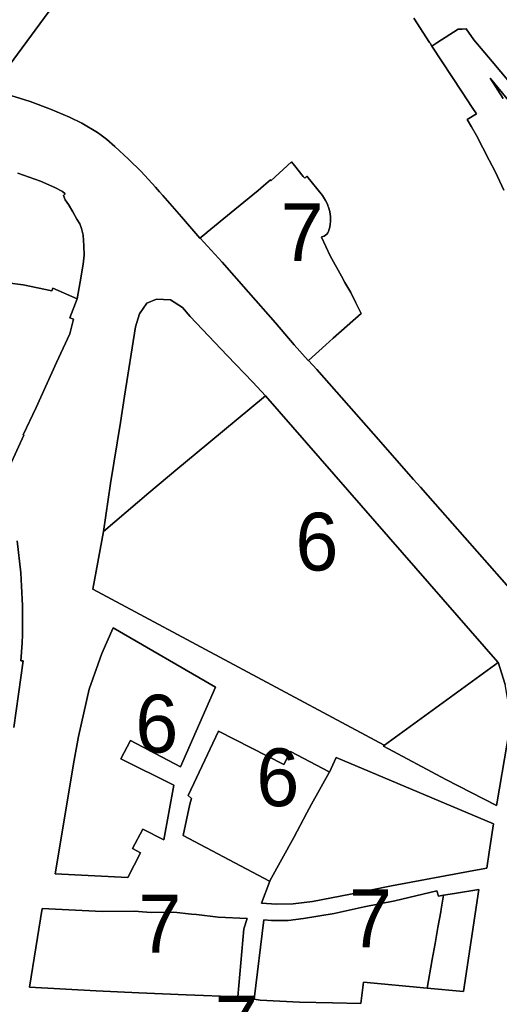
# Model space of a CAD drawing. Extents: x 598968 to 613553, y 4409678 to 4430833.
# Drawn here: x 607378.5 to 607478.1, y 4416577.8 to 4416782.2 of the extents above; entities that cross this region are included whole.
import ezdxf

# ---------------------------------------------------------------- set-up
doc = ezdxf.new("R2010")
doc.units = 0
for name, color, linetype in [('1', 7, 'Continuous'), ('ZONA 2. CARRERS DE CASES. Cases de trast', 7, 'Continuous'), ('ZONA 6. EDIFICIS DE PISOS_ AÏLLATS I EN PARCEL.LES', 7, 'Continuous'), ('ZONA 7. CONJUNTS AMB ORDENACIONS ESPECÍFIQUES', 7, 'Continuous')]:
    doc.layers.add(name, color=color, linetype=linetype)

msp = doc.modelspace()

# ---------------------------------------------------------------- linework, layer by layer
at = {"layer": '1'}
for points in [[(607386.3243, 4416786.4145), (607372.5667, 4416767.6727), (607380.6335, 4416765.184), (607384.899, 4416763.6217), (607388.8289, 4416761.9318), (607391.3789, 4416760.6968), (607394.6589, 4416758.7519), (607395.4182, 4416758.1945), (607396.5093, 4416757.3936), (607398.2639, 4416755.862), (607401.1232, 4416753.2226), (607403.6938, 4416750.6721), (607406.7038, 4416747.4072), (607407.5059, 4416746.4781), (607408.2188, 4416745.6523), (607412.0788, 4416741.2424), (607415.9387, 4416736.8325), (607416.8851, 4416737.6114), (607417.4087, 4416738.0525), (607422.4268, 4416742.1721), (607425.0586, 4416744.3326), (607428.0586, 4416746.7226), (607429.1484, 4416747.704), (607430.6111, 4416748.9097), (607430.6985, 4416748.7604), (607434.9485, 4416752.7027), (607435.5801, 4416751.9204), (607437.4068, 4416749.6585), (607437.7184, 4416749.2727), (607437.944, 4416749.5035), (607438.1484, 4416749.7127), (607441.4284, 4416745.7128), (607442.0615, 4416744.6782), (607442.2899, 4416744.144), (607442.5094, 4416743.6507), (607442.5292, 4416743.5844), (607442.5384, 4416743.5629), (607442.6357, 4416743.2431), (607442.913, 4416742.332), (607442.9859, 4416741.7542), (607443.0509, 4416741.3987), (607443.0558, 4416741.1996), (607443.074, 4416741.0555), (607443.0646, 4416740.8449), (607443.0795, 4416740.246), (607443.0168, 4416739.7702), (607443.016, 4416739.7653), (607442.9284, 4416739.103), (607442.7434, 4416738.513), (607442.6391, 4416738.2084), (607442.4863, 4416737.9251), (607442.2891, 4416737.6706), (607442.053, 4416737.4518), (607441.7842, 4416737.2746), (607441.4901, 4416737.1434), (607441.2801, 4416737.0892), (607441.1784, 4416737.0629), (607442.0734, 4416735.103), (607442.9684, 4416733.143), (607445.3421, 4416728.9189), (607446.0534, 4416727.6531), (607447.2584, 4416725.5632), (607448.3584, 4416723.3782), (607449.3103, 4416721.4874), (607449.4584, 4416721.1933), (607446.5484, 4416718.6383), (607443.5885, 4416716.0332), (607442.1085, 4416714.7132), (607438.4787, 4416711.4215), (607440.2385, 4416709.5332), (607451.9935, 4416696.2036), (607460.3291, 4416686.7515), (607461.737, 4416685.155), (607465.8801, 4416680.4569), (607481.2278, 4416663.0529)], [(607372.5667, 4416767.6727), (607386.3243, 4416786.4145)], [(607460.3682, 4416782.4727), (607463.6508, 4416777.477), (607463.7616, 4416777.3084), (607464.1451, 4416776.7248), (607465.1361, 4416777.3659), (607469.5681, 4416780.233), (607470.4381, 4416780.253), (607471.228, 4416780.283), (607472.858, 4416777.973), (607476.6384, 4416773.4786), (607488.1231, 4416759.8249)], [(607479.0966, 4416746.7706), (607477.3231, 4416750.5584), (607476.0581, 4416753.0034), (607474.7181, 4416755.5633), (607473.3781, 4416758.1233), (607472.3422, 4416759.9156), (607471.4381, 4416761.4832), (607473.3881, 4416762.6532), (607472.5181, 4416763.9732), (607470.4281, 4416767.1631), (607464.1451, 4416776.7248), (607463.7616, 4416777.3084), (607463.6508, 4416777.477), (607460.3682, 4416782.4727)], [(607488.1231, 4416759.8249), (607476.6384, 4416773.4786), (607472.858, 4416777.973), (607471.228, 4416780.283), (607470.4381, 4416780.253), (607469.5681, 4416780.233), (607465.1361, 4416777.3659), (607464.1451, 4416776.7248), (607470.4281, 4416767.1631), (607472.5181, 4416763.9732), (607473.3881, 4416762.6532), (607471.4381, 4416761.4832), (607472.3422, 4416759.9156), (607473.3781, 4416758.1233), (607474.7181, 4416755.5633), (607476.0581, 4416753.0034), (607477.3231, 4416750.5584), (607479.0966, 4416746.7706)], [(607478.9204, 4416765.8107), (607476.2357, 4416770.0207), (607480.3837, 4416764.9799)], [(607480.3837, 4416764.9799), (607476.2357, 4416770.0207), (607478.9204, 4416765.8107)], [(607481.2278, 4416663.0529), (607465.8801, 4416680.4569), (607461.737, 4416685.155), (607460.3291, 4416686.7515), (607451.9935, 4416696.2036), (607440.2385, 4416709.5332), (607438.4787, 4416711.4215), (607438.4586, 4416711.4032), (607435.5186, 4416714.6931), (607431.6186, 4416719.213), (607426.0286, 4416725.6228), (607420.5887, 4416731.8127), (607415.9607, 4416736.8325), (607415.9387, 4416736.8325), (607412.0788, 4416741.2424), (607408.2188, 4416745.6523), (607407.5059, 4416746.4781), (607406.7038, 4416747.4072), (607403.6938, 4416750.6721), (607401.1232, 4416753.2226), (607398.2639, 4416755.862), (607396.5093, 4416757.3936), (607395.4182, 4416758.1945), (607394.6589, 4416758.7519), (607391.3789, 4416760.6968), (607388.8289, 4416761.9318), (607384.899, 4416763.6217), (607380.6335, 4416765.184), (607372.5667, 4416767.6727)], [(607375.9492, 4416727.5319), (607379.1992, 4416727.122), (607385.1291, 4416725.8721), (607385.3691, 4416726.4321), (607390.4491, 4416724.2122), (607391.049, 4416727.7322), (607391.669, 4416731.4322), (607391.879, 4416733.2821), (607391.789, 4416735.2221), (607391.699, 4416737.4321), (607391.339, 4416738.8321), (607390.969, 4416739.782), (607390.329, 4416740.772), (607389.549, 4416742.262), (607388.629, 4416743.842), (607387.919, 4416744.7819), (607387.579, 4416745.6519), (607387.8994, 4416746.0624), (607387.349, 4416746.4919), (607385.809, 4416747.3719), (607382.8291, 4416748.6718), (607378.1191, 4416750.2917)], [(607378.1191, 4416750.2917), (607382.8291, 4416748.6718), (607385.809, 4416747.3719), (607387.349, 4416746.4919), (607387.8994, 4416746.0624), (607387.579, 4416745.6519), (607387.919, 4416744.7819), (607388.629, 4416743.842), (607389.549, 4416742.262), (607390.329, 4416740.772), (607390.969, 4416739.782), (607391.339, 4416738.8321), (607391.699, 4416737.4321), (607391.789, 4416735.2221), (607391.879, 4416733.2821), (607391.669, 4416731.4322), (607391.049, 4416727.7322), (607390.4491, 4416724.2122), (607388.8791, 4416720.2722), (607389.6691, 4416719.9923), (607388.8791, 4416716.9523), (607386.1492, 4416711.0223), (607381.8792, 4416701.6823), (607379.1993, 4416695.9624), (607379.3593, 4416695.8924), (607376.4393, 4416689.5524)], [(607479.6885, 4416631.5449), (607477.7042, 4416619.78), (607477.5785, 4416619.035), (607467.0586, 4416624.4047), (607454.0687, 4416631.3444), (607454.2157, 4416631.5745), (607393.6692, 4416663.953), (607395.9292, 4416675.9129), (607397.3552, 4416685.8582), (607399.4308, 4416698.5534), (607400.2864, 4416704.0086), (607402.5439, 4416718.4025), (607403.3889, 4416721.0975), (607404.8689, 4416723.3525), (607406.8889, 4416724.1925), (607409.8088, 4416723.9926), (607412.3288, 4416722.4226), (607413.8888, 4416720.5527), (607421.6006, 4416712.4978), (607426.9452, 4416706.9156), (607429.5508, 4416704.0995), (607477.844, 4416648.7799), (607477.8784, 4416648.8046), (607479.3796, 4416644.1495)], [(607377.9694, 4416673.9526), (607378.7194, 4416667.3727), (607378.8894, 4416664.5627), (607379.0494, 4416660.5728), (607379.0694, 4416654.5328), (607378.9794, 4416652.7128), (607378.7095, 4416649.1029), (607379.2295, 4416649.0829), (607377.2595, 4416635.2131)]]:
    msp.add_lwpolyline(points, dxfattribs=at)
for points in [[(607429.5508, 4416704.0995), (607426.9452, 4416706.9156), (607421.6006, 4416712.4978), (607413.8888, 4416720.5527), (607412.3288, 4416722.4226), (607409.8088, 4416723.9926), (607406.8889, 4416724.1925), (607404.8689, 4416723.3525), (607403.3889, 4416721.0975), (607402.5439, 4416718.4025), (607400.2864, 4416704.0086), (607399.4308, 4416698.5534), (607397.3552, 4416685.8582), (607395.9292, 4416675.9129), (607405.2975, 4416683.9329), (607411.3642, 4416688.9774), (607414.9525, 4416691.961)], [(607389.7794, 4416628.4334), (607390.6994, 4416633.3733), (607392.9093, 4416643.1632), (607395.5593, 4416650.6132), (607397.9292, 4416655.9231), (607419.159, 4416643.6037), (607411.9192, 4416627.0538), (607401.4993, 4416632.5135), (607399.4693, 4416628.7435), (607410.5292, 4416623.2638), (607408.4293, 4416611.8939), (607404.0593, 4416614.1038), (607401.8898, 4416610.1073), (607403.6203, 4416609.1946), (607400.9294, 4416604.1138), (607385.8695, 4416604.8636)], [(607454.2157, 4416631.5745), (607454.0687, 4416631.3444), (607467.0586, 4416624.4047), (607477.5785, 4416619.035), (607477.7042, 4416619.78), (607479.6885, 4416631.5449), (607480.1985, 4416634.4299), (607480.1683, 4416638.1557), (607480.1589, 4416639.3209), (607479.3796, 4416644.1495), (607477.8784, 4416648.8046), (607477.844, 4416648.7799), (607477.8941, 4416648.7225), (607454.2707, 4416631.5451)], [(607419.789, 4416634.4738), (607433.3389, 4416627.5141), (607434.7889, 4416630.2541), (607442.7547, 4416626.0153), (607442.8405, 4416625.9719), (607444.2588, 4416628.9943), (607476.9429, 4416615.2265), (607476.0333, 4416609.3501), (607475.5186, 4416606.0251), (607472.817, 4416605.5206), (607455.7587, 4416602.3348), (607447.1988, 4416600.6347), (607439.2952, 4416599.1174), (607435.3243, 4416598.6072), (607431.8781, 4416598.5646), (607428.7091, 4416598.7344), (607430.4581, 4416603.3147), (607430.419, 4416603.3344), (607412.4792, 4416612.8139), (607413.8292, 4416619.3339), (607414.1492, 4416620.5039), (607413.4892, 4416621.0839)], [(607430.4581, 4416603.3147), (607428.7091, 4416598.7344), (607431.8781, 4416598.5646), (607435.3243, 4416598.6072), (607439.2952, 4416599.1174), (607447.1988, 4416600.6347), (607455.7587, 4416602.3348), (607472.817, 4416605.5206), (607475.5186, 4416606.0251), (607476.0333, 4416609.3501), (607476.9429, 4416615.2265), (607444.2588, 4416628.9943), (607442.8405, 4416625.9719), (607442.8088, 4416625.9043), (607439.1115, 4416619.3166), (607438.1407, 4416617.5317), (607435.415, 4416612.386), (607430.4905, 4416603.3996)], [(607473.8586, 4416601.6051), (607470.6758, 4416580.433), (607463.1388, 4416581.1352), (607449.9389, 4416582.3649), (607449.3489, 4416577.895), (607443.469, 4416578.0349), (607436.629, 4416578.2048), (607428.4491, 4416578.6346), (607427.2092, 4416578.8046), (607429.2091, 4416595.3144), (607430.8191, 4416595.1845), (607434.239, 4416595.1745), (607437.489, 4416595.5946), (607443.7989, 4416596.5747), (607450.0888, 4416598.0048), (607456.4487, 4416599.2349), (607465.1687, 4416601.325), (607465.4987, 4416600.205), (607466.5787, 4416600.385), (607468.8193, 4416600.7606)], [(607463.1388, 4416581.1352), (607470.6758, 4416580.433), (607473.8586, 4416601.6051), (607468.8193, 4416600.7606), (607466.5787, 4416600.385), (607466.0741, 4416597.4919), (607465.9787, 4416596.945), (607465.3966, 4416593.6921), (607464.8052, 4416590.3876), (607464.2088, 4416587.0551)], [(607425.0391, 4416593.4244), (607423.7892, 4416579.3345), (607413.0993, 4416579.7343), (607403.2194, 4416580.1242), (607394.3695, 4416580.584), (607380.5397, 4416581.2938), (607383.1696, 4416597.6636), (607395.6395, 4416597.0238), (607402.2494, 4416597.0639), (607404.8993, 4416596.864), (607405.9193, 4416596.794), (607410.4793, 4416596.8841), (607414.1492, 4416596.5042), (607415.1992, 4416596.3942), (607419.6992, 4416595.8543), (607425.7591, 4416595.5944)]]:
    msp.add_lwpolyline(points, close=True, dxfattribs=at)
at = {"layer": 'ZONA 2. CARRERS DE CASES. Cases de trast'}
for points in [[(607376.4393, 4416689.5524), (607379.3593, 4416695.8924), (607379.1993, 4416695.9624), (607381.8792, 4416701.6823), (607386.1492, 4416711.0223), (607388.8791, 4416716.9523), (607389.6691, 4416719.9923), (607388.8791, 4416720.2722), (607390.4491, 4416724.2122), (607385.3691, 4416726.4321), (607385.1291, 4416725.8721), (607379.1992, 4416727.122), (607375.9492, 4416727.5319)], [(607377.2595, 4416635.2131), (607379.2295, 4416649.0829), (607378.7095, 4416649.1029), (607378.9794, 4416652.7128), (607379.0694, 4416654.5328), (607379.0494, 4416660.5728), (607378.8894, 4416664.5627), (607378.7194, 4416667.3727), (607377.9694, 4416673.9526)]]:
    msp.add_lwpolyline(points, dxfattribs=at)
at = {"layer": 'ZONA 6. EDIFICIS DE PISOS_ AÏLLATS I EN PARCEL.LES'}
for points in [[(607477.844, 4416648.7799), (607429.5508, 4416704.0995), (607414.9525, 4416691.961), (607411.3642, 4416688.9774), (607405.2975, 4416683.9329), (607395.9292, 4416675.9129), (607393.6692, 4416663.953), (607454.2157, 4416631.5745), (607454.2707, 4416631.5451), (607477.8941, 4416648.7225)], [(607419.159, 4416643.6037), (607397.9292, 4416655.9231), (607395.5593, 4416650.6132), (607392.9093, 4416643.1632), (607390.6994, 4416633.3733), (607389.7794, 4416628.4334), (607385.8695, 4416604.8636), (607400.9294, 4416604.1138), (607403.6203, 4416609.1946), (607401.8898, 4416610.1073), (607404.0593, 4416614.1038), (607408.4293, 4416611.8939), (607410.5292, 4416623.2638), (607399.4693, 4416628.7435), (607401.4993, 4416632.5135), (607411.9192, 4416627.0538)], [(607442.8405, 4416625.9719), (607442.7547, 4416626.0153), (607434.7889, 4416630.2541), (607433.3389, 4416627.5141), (607419.789, 4416634.4738), (607413.4892, 4416621.0839), (607414.1492, 4416620.5039), (607413.8292, 4416619.3339), (607412.4792, 4416612.8139), (607430.419, 4416603.3344), (607430.4581, 4416603.3147), (607430.4905, 4416603.3996), (607435.415, 4416612.386), (607438.1407, 4416617.5317), (607439.1115, 4416619.3166), (607442.8088, 4416625.9043)]]:
    msp.add_lwpolyline(points, close=True, dxfattribs=at)
at = {"layer": 'ZONA 7. CONJUNTS AMB ORDENACIONS ESPECÍFIQUES'}
for points in [[(607438.4787, 4416711.4215), (607442.1085, 4416714.7132), (607443.5885, 4416716.0332), (607446.5484, 4416718.6383), (607449.4584, 4416721.1933), (607449.3103, 4416721.4874), (607448.3584, 4416723.3782), (607447.2584, 4416725.5632), (607446.0534, 4416727.6531), (607445.3421, 4416728.9189), (607442.9684, 4416733.143), (607442.0734, 4416735.103), (607441.1784, 4416737.0629), (607441.2801, 4416737.0892), (607441.4901, 4416737.1434), (607441.7842, 4416737.2746), (607442.053, 4416737.4518), (607442.2891, 4416737.6706), (607442.4863, 4416737.9251), (607442.6391, 4416738.2084), (607442.7434, 4416738.513), (607442.9284, 4416739.103), (607443.016, 4416739.7653), (607443.0168, 4416739.7702), (607443.0795, 4416740.246), (607443.0646, 4416740.8449), (607443.074, 4416741.0555), (607443.0558, 4416741.1996), (607443.0509, 4416741.3987), (607442.9859, 4416741.7542), (607442.913, 4416742.332), (607442.6357, 4416743.2431), (607442.5384, 4416743.5629), (607442.5292, 4416743.5844), (607442.5094, 4416743.6507), (607442.2899, 4416744.144), (607442.0615, 4416744.6782), (607441.4284, 4416745.7128), (607438.1484, 4416749.7127), (607437.944, 4416749.5035), (607437.7184, 4416749.2727), (607437.4068, 4416749.6585), (607435.5801, 4416751.9204), (607434.9485, 4416752.7027), (607430.6985, 4416748.7604), (607430.6111, 4416748.9097), (607429.1484, 4416747.704), (607428.0586, 4416746.7226), (607425.0586, 4416744.3326), (607422.4268, 4416742.1721), (607417.4087, 4416738.0525), (607416.8851, 4416737.6114), (607415.9387, 4416736.8325), (607415.9607, 4416736.8325), (607420.5887, 4416731.8127), (607426.0286, 4416725.6228), (607431.6186, 4416719.213), (607435.5186, 4416714.6931), (607438.4586, 4416711.4032)], [(607466.5787, 4416600.385), (607465.4987, 4416600.205), (607465.1687, 4416601.325), (607456.4487, 4416599.2349), (607450.0888, 4416598.0048), (607443.7989, 4416596.5747), (607437.489, 4416595.5946), (607434.239, 4416595.1745), (607430.8191, 4416595.1845), (607429.2091, 4416595.3144), (607427.2092, 4416578.8046), (607428.4491, 4416578.6346), (607436.629, 4416578.2048), (607443.469, 4416578.0349), (607449.3489, 4416577.895), (607449.9389, 4416582.3649), (607463.1388, 4416581.1352), (607464.2088, 4416587.0551), (607464.8052, 4416590.3876), (607465.3966, 4416593.6921), (607465.9787, 4416596.945), (607466.0741, 4416597.4919)], [(607383.1696, 4416597.6636), (607380.5397, 4416581.2938), (607394.3695, 4416580.584), (607403.2194, 4416580.1242), (607413.0993, 4416579.7343), (607423.7892, 4416579.3345), (607425.0391, 4416593.4244), (607425.7591, 4416595.5944), (607419.6992, 4416595.8543), (607415.1992, 4416596.3942), (607414.1492, 4416596.5042), (607410.4793, 4416596.8841), (607405.9193, 4416596.794), (607404.8993, 4416596.864), (607402.2494, 4416597.0639), (607395.6395, 4416597.0238)]]:
    msp.add_lwpolyline(points, close=True, dxfattribs=at)

# ---------------------------------------------------------------- texts
at = {"layer": 'ZONA 6. EDIFICIS DE PISOS_ AÏLLATS I EN PARCEL.LES'}
for p in [(607435.7817, 4416667.8223), (607402.5143, 4416630.0185), (607427.6598, 4416618.8942)]:
    msp.add_text('6', height=12, dxfattribs=at).set_placement(p)
at = {"layer": 'ZONA 7. CONJUNTS AMB ORDENACIONS ESPECÍFIQUES'}
for p in [(607432.6985, 4416732.053), (607446.894, 4416589.61), (607403.1494, 4416588.499), (607419.0194, 4416567.5443)]:
    msp.add_text('7', height=12, dxfattribs=at).set_placement(p)

doc.saveas('drawing.dxf')
